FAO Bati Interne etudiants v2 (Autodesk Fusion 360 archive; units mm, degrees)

design "FAO Bati Interne etudiants" references "brut bati", "Bati-interne"
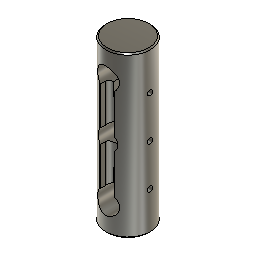
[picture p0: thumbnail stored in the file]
component_insert "Insertion d'un composant1"
component_insert "Insertion d'un composant2"
joint "Assembler" alignOffsetX 0 alignOffsetY 0 alignOffsetZ -15
work_plane "Plan de construction"
work_axis "Axe de construction1"
work_axis "Axe de construction2"
work_point "WorkPoint2"
work_point "WorkPoint3"
sketch "Esquisse" plane through (0, -7.15, -81.7337) normal (0, -1, 0) x axis (1, 0, 0)
  line L1 (0, 52.2337) -> (0, 136.2337)
  point P2 (0, 136.2337)
  point P4 (0, 136.2337)
  point P3 (0, 52.2337)
  point P5 (0, 52.2337)
  coincident P2 P4
  coincident P3 P5

design "Bati-interne"
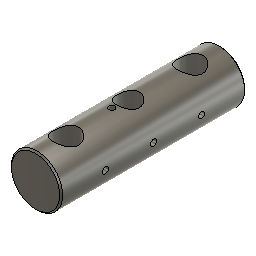
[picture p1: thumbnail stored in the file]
parameter "Entraxe_Ref" = 84
work_plane "Plan de construction1" AlongDistance 42 (= "Entraxe_Ref / 2")
sketch "Esquisse1" plane through (0, 0, 0) normal (0, 1, 0) x axis (1, 0, 0)
  line L1 (17.325, 0) -> (0, 0)
  line L2 (17.325, -62.5) -> (17.325, 0)
  line L3 (0, -62.5) -> (17.325, -62.5)
  line L4 (0, 0) -> (0, -62.5)
  line L5 (9.4095, -42) -> (0.3245, -42)
  point P1 (0, 0)
  point P2 (0, 0)
  point P4 (17.325, -62.5)
  point P5 (0, -62.5)
  horizontal L1
  vertical L2
  horizontal L3
  vertical L4
  coincident P1 P2
  dimension "d2" distance P4 P5 = 17.325 (= "( 34.65 / 2 ) * 1 mm")
  dimension "d3" distance L3 L5 = 20.5
revolve "Révolution" sketch "Esquisse1"
sketch "Esquisse2" plane through (0, 0, 0) normal (0, 1, 0) x axis (1, 0, 0)
  line L1 (0, -22.5) -> (0, -1.75)
  line L2 (9.4095, -42) -> (0.3245, -42)
  circle C1 centre (0, -42) radius 8.5
  point P2 (0, -42)
  coincident P2 L1
  coincident P2 L2
  dimension "d5" diameter C1 = 17
extrude "Extrusion1" cut sketch "Esquisse2" profile of C1 "d7" 0 (= "Side2TaperAngle")
sketch "Esquisse3" plane through (0, 0, 0) normal (0, 0, 1) x axis (1, 0, 0)
  line L1 (-5.15, -17.325) -> (-5.15, -12.3)
  line L2 (5.15, -17.325) -> (-5.15, -17.325)
  line L3 (5.15, -17.325) -> (5.15, -12.3)
  line L4 (0, 22.5) -> (0, 1.75)
  line L5 (22.5, 0) -> (1.75, 0)
  arc A1 centre (0, -12.3) radius 5.15 clockwise from (-5.15, -12.3) to (5.15, -12.3)
  circle C1 centre (0, 0) radius 17.325
  point P2 (0, -12.3)
  perpendicular L1 L2
  perpendicular L2 L3
  tangent L3 A1
  tangent L1 A1
  tangent L2 C1
  coincident P2 L4
  vertical L3
  dimension "d8" distance L1 L3 = 10.3
  dimension "d9" distance P2 L5 = 12.3
extrude "Extrusion2" cut sketch "Esquisse3" profile of A1 L1 L3 C1 to an object
work_plane "Plan de construction2" AlongDistance -1
sketch "Esquisse4" plane through (0, -1, 0) normal (0, 1, 0) x axis (1, 0, 0)
  line L1 (3, -24.5) -> (3, -38.5)
  line L2 (-3, -38.5) -> (-3, -24.5)
  line L3 (0, -24.5) -> (0, -38.5)
  line L4 (5.15, 0) -> (5.15, -35.2378)
  line L5 (22.5, 0) -> (1.75, 0)
  arc A1 centre (0, -24.5) radius 3 clockwise from (-3, -24.5) to (3, -24.5)
  arc A2 centre (0, -38.5) radius 3 clockwise from (3, -38.5) to (-3, -38.5)
  point P1 (0, 0)
  point P6 (0, -38.5)
  point P7 (0, -24.5)
  tangent L1 A1
  tangent A1 L2
  parallel L1 L2
  tangent L2 A2
  tangent L1 A2
  parallel L3 L4
  coincident P1 L3
  dimension "d13" distance P6 P7 = 14
  dimension "d14" distance P7 L5 = 24.5 (= "( 49 / 2 ) * 1 mm")
  dimension "d18" distance L1 L2 = 6
extrude "Extrusion3" cut sketch "Esquisse4" profile of L1 A1 L2 A2
work_plane "Plan de construction3"
sketch "Esquisse5" plane through (17.325, 0, 41.25) normal (1, 0, 0) x axis (0, 0, -1)
  line L1 (18.75, 0) -> (39.5, 0)
  line L2 (-0.75, 0.3245) -> (-0.75, 9.4095)
  circle C1 centre (8.75, 0) radius 2
  point P2 (8.75, 0)
  coincident P2 L1
  dimension "d20" diameter C1 = 4
  dimension "d21" distance P2 L2 = 9.5
extrude "Extrusion4" cut sketch "Esquisse5" profile of C1 against normal blind 5
chamfer "Chanfrein1" distance 1
chamfer "Chanfrein2" distance 0.5
mirror "Symétrie miroir" mirrorStitchTolerance 0.1
sketch "Esquisse6" plane through (0, 0, 0) normal (0, 1, 0) x axis (1, 0, 0)
  circle C1 centre (0, 0) radius 7.6
  point P1 (0, 0)
  point P2 (0, 0)
  coincident P1 P2
  dimension "d28" diameter C1 = 15.2
extrude "Extrusion5" cut sketch "Esquisse6" "d30" 0 (= "Side2TaperAngle")
sketch "Esquisse7" plane through (0, 0, 0) normal (1, 0, 0) x axis (0, 0, -1)
  line L1 (0, 22.5) -> (0, 1.75)
  line L2 (-22.5, 0) -> (-1.75, 0)
  circle C1 centre (0, 0) radius 2.05
  point P2 (0, 0)
  coincident P2 L1
  coincident P2 L2
  dimension "d31" diameter C1 = 4.1
extrude "Extrusion6" cut sketch "Esquisse7" profile of C1
work_plane "Plan de construction4"
sketch "Esquisse8" plane through (0, 17.325, 0) normal (0, 1, 0) x axis (1, 0, 0)
  line L1 (0, -22.5) -> (0, -1.75)
  line L2 (22.5, 0) -> (1.75, 0)
  circle C1 centre (0, -11) radius 2.05
  point P2 (0, -11)
  coincident P2 L1
  dimension "d34" distance P2 L2 = 11
  dimension "d35" diameter C1 = 4.1
extrude "Extrusion7" cut sketch "Esquisse8" profile of C1 L1 against normal blind 10
hole "Perçage" HoleDepth 10 HoleDiameter 4.1

design "brut bati"
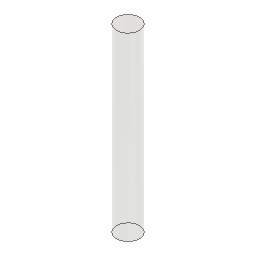
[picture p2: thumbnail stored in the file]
sketch "Esquisse" plane through (0, 0, 0) normal (0, 0, 1) x axis (1, 0, 0)
  circle C1 centre (0, 0) radius 17.75
  point P1 (0, 0)
  point P2 (0, 0)
  coincident P1 P2
  dimension "d1" diameter C1 = 35.5
extrude "Extrusion" new body sketch "Esquisse" along normal blind 280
